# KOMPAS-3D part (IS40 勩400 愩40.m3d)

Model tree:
1. Плоскость XY
2. Плоскость ZX
3. Плоскость ZY
4. Ось X
5. Ось Y
6. Ось Z
7. Начало координат
8. Операция без истории:1

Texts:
  133 1 134 1 135 1 136 0 50 1|SPDS|133 1 134 1 135 1 136 0 50 1
  125 1 126 1 127 1 128 0 50 1|SPDS|125 1 126 1 127 1 128 0 50 1
  129 1 130 1 131 1 132 0 50 1|SPDS|129 1 130 1 131 1 132 0 50 1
